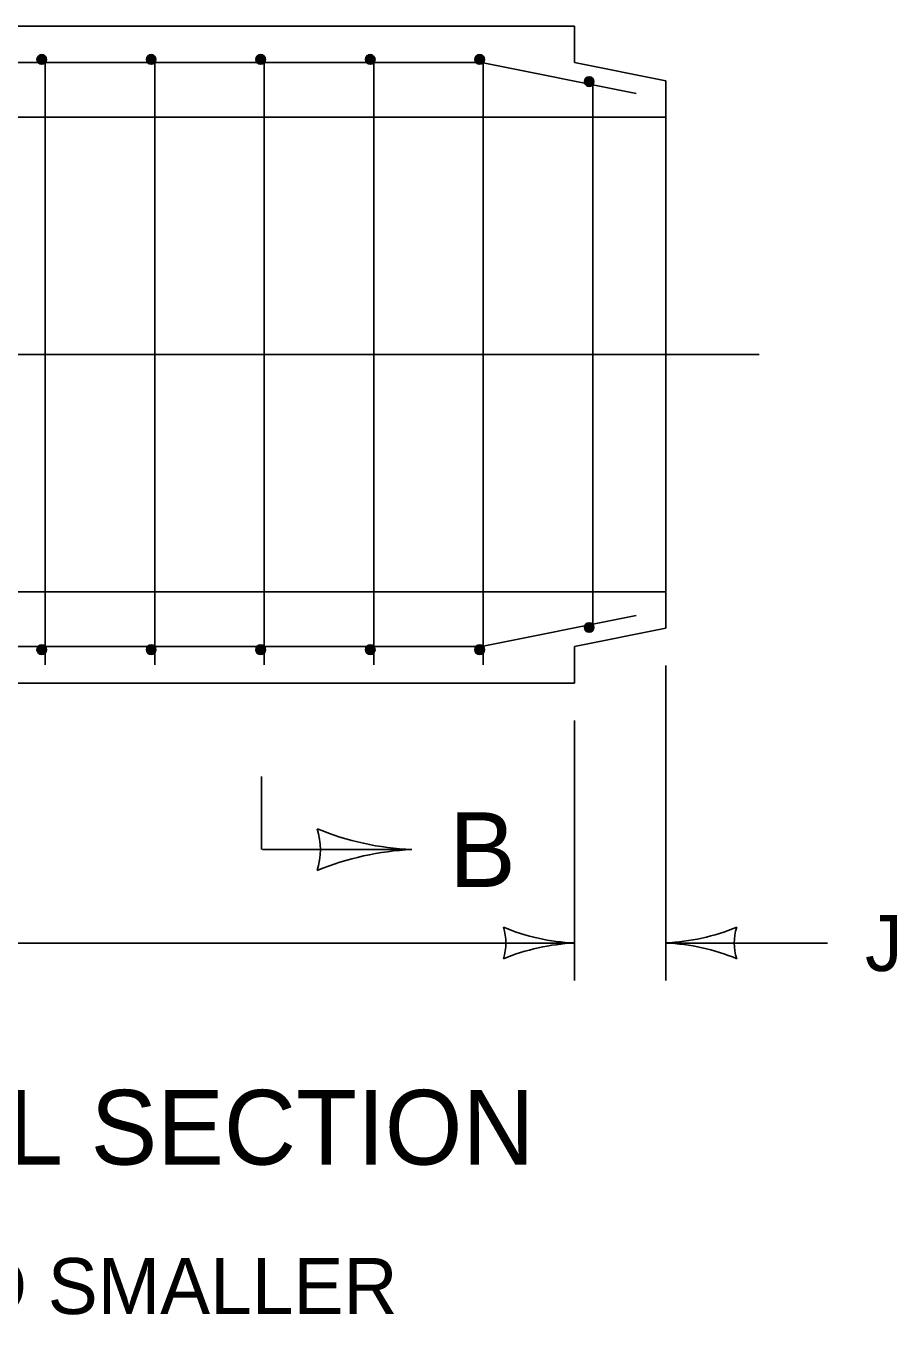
# Model space of a CAD drawing. Extents: x 49991.4 to 50021, y 49987.6 to 50011.4.
# Drawn here: x 50010.952 to 50011.884, y 49993.48 to 49994.877 of the extents above; entities that cross this region are included whole.
import ezdxf

# ---------------------------------------------------------------- set-up
doc = ezdxf.new("R2010")
doc.units = 0
for name, color, linetype in [('Level 1', 7, 'Continuous'), ('Level 2', 7, 'Continuous'), ('Level 3', 7, 'Continuous'), ('Level 5', 7, 'Continuous'), ('Level 6', 7, 'Continuous')]:
    doc.layers.add(name, color=color, linetype=linetype)

msp = doc.modelspace()

# ---------------------------------------------------------------- linework, layer by layer
at = {"layer": 'Level 1'}
for p, q in [((50011.5389, 49994.8774), (50009.7605, 49994.8774)), ((50011.5389, 49994.8384), (50011.5389, 49994.8774)), ((50011.4393, 49994.8384), (50009.9169, 49994.8384)), ((50010.9722, 49994.8384), (50010.9722, 49994.1934)), ((50011.0895, 49994.8384), (50011.0895, 49994.1934)), ((50011.2067, 49994.8384), (50011.2067, 49994.1934)), ((50011.3239, 49994.8384), (50011.3239, 49994.1934)), ((50011.4393, 49994.8384), (50011.6051, 49994.8052)), ((50011.4412, 49994.8384), (50011.4412, 49994.1934)), ((50011.5389, 49994.8384), (50011.6367, 49994.8188)), ((50011.6367, 49994.2326), (50011.6367, 49994.8188)), ((50011.5585, 49994.8145), (50011.5585, 49994.2368)), ((50011.6367, 49994.7798), (50009.8583, 49994.7798)), ((50011.6367, 49994.2716), (50009.8583, 49994.2716)), ((50011.4393, 49994.213), (50011.6051, 49994.2462)), ((50011.6367, 49994.2326), (50011.5389, 49994.213)), ((50011.4393, 49994.213), (50009.9169, 49994.213)), ((50011.5389, 49994.1739), (50011.5389, 49994.213)), ((50011.5389, 49994.1739), (50009.7605, 49994.1739))]:
    msp.add_line(p, q, dxfattribs=at)
for points in [[(50010.9633, 49994.8422), (50010.9679, 49994.8469)], [(50010.9633, 49994.8414), (50010.9688, 49994.8469)], [(50010.9634, 49994.8406), (50010.9695, 49994.8468)], [(50010.9635, 49994.8432), (50010.9669, 49994.8467)], [(50010.9636, 49994.84), (50010.9701, 49994.8466)], [(50010.9639, 49994.8394), (50010.9707, 49994.8464)], [(50010.9641, 49994.8389), (50010.9713, 49994.846)], [(50010.9643, 49994.8449), (50010.9653, 49994.8458), (50010.9653, 49994.8458)], [(50010.9645, 49994.8384), (50010.9645, 49994.8384), (50010.9717, 49994.8457), (50010.9717, 49994.8457)], [(50010.9649, 49994.838), (50010.9649, 49994.838), (50010.9721, 49994.8452), (50010.9721, 49994.8452)], [(50010.9654, 49994.8376), (50010.9725, 49994.8448)], [(50010.9659, 49994.8373), (50010.9729, 49994.8442)], [(50011.0805, 49994.8422), (50011.0852, 49994.8469)], [(50011.0805, 49994.8414), (50011.0861, 49994.8469)], [(50011.0807, 49994.8406), (50011.0868, 49994.8468)], [(50011.0807, 49994.8432), (50011.0842, 49994.8467)], [(50011.0809, 49994.84), (50011.0874, 49994.8466)], [(50011.0811, 49994.8394), (50011.088, 49994.8464)], [(50011.0815, 49994.8389), (50011.0885, 49994.846)], [(50011.0816, 49994.8449), (50011.0825, 49994.8458), (50011.0825, 49994.8458)], [(50011.0817, 49994.8384), (50011.0818, 49994.8384), (50011.0889, 49994.8457), (50011.089, 49994.8457)], [(50011.0821, 49994.838), (50011.0821, 49994.838), (50011.0894, 49994.8452), (50011.0894, 49994.8452)], [(50011.0827, 49994.8376), (50011.0897, 49994.8448)], [(50011.0831, 49994.8373), (50011.0901, 49994.8442)], [(50011.1978, 49994.8422), (50011.2025, 49994.8469)], [(50011.1978, 49994.8414), (50011.2033, 49994.8469)], [(50011.1979, 49994.8406), (50011.2041, 49994.8468)], [(50011.198, 49994.8432), (50011.2015, 49994.8467)], [(50011.1981, 49994.84), (50011.2047, 49994.8466)], [(50011.1983, 49994.8394), (50011.2053, 49994.8464)], [(50011.1987, 49994.8389), (50011.2057, 49994.846)], [(50011.1989, 49994.8449), (50011.1997, 49994.8458), (50011.1998, 49994.8458)], [(50011.199, 49994.8384), (50011.1991, 49994.8384), (50011.2063, 49994.8457), (50011.2063, 49994.8457)], [(50011.1995, 49994.838), (50011.1995, 49994.838), (50011.2067, 49994.8452), (50011.2067, 49994.8452)], [(50011.1999, 49994.8376), (50011.207, 49994.8448)], [(50011.2004, 49994.8373), (50011.2073, 49994.8442)], [(50011.3151, 49994.8422), (50011.3197, 49994.8469)], [(50011.3151, 49994.8414), (50011.3205, 49994.8469)], [(50011.3151, 49994.8406), (50011.3213, 49994.8468)], [(50011.3153, 49994.8432), (50011.3187, 49994.8467)], [(50011.3153, 49994.84), (50011.3219, 49994.8466)], [(50011.3157, 49994.8394), (50011.3225, 49994.8464)], [(50011.3159, 49994.8389), (50011.323, 49994.846)], [(50011.3161, 49994.8449), (50011.317, 49994.8458), (50011.3171, 49994.8458)], [(50011.3163, 49994.8384), (50011.3163, 49994.8384), (50011.3235, 49994.8457), (50011.3235, 49994.8457)], [(50011.3167, 49994.838), (50011.3167, 49994.838), (50011.3239, 49994.8452), (50011.3239, 49994.8452)], [(50011.3171, 49994.8376), (50011.3243, 49994.8448)], [(50011.3177, 49994.8373), (50011.3246, 49994.8442)], [(50011.4323, 49994.8422), (50011.437, 49994.8469)], [(50011.4323, 49994.8414), (50011.4378, 49994.8469)], [(50011.4324, 49994.8406), (50011.4385, 49994.8468)], [(50011.4325, 49994.8432), (50011.4359, 49994.8467)], [(50011.4326, 49994.84), (50011.4391, 49994.8466)], [(50011.4329, 49994.8394), (50011.4397, 49994.8464)], [(50011.4332, 49994.8389), (50011.4403, 49994.846)], [(50011.4333, 49994.8449), (50011.4343, 49994.8458), (50011.4343, 49994.8458)], [(50011.4335, 49994.8384), (50011.4335, 49994.8384), (50011.4407, 49994.8457), (50011.4408, 49994.8457)], [(50011.4339, 49994.838), (50011.4339, 49994.838), (50011.4411, 49994.8452), (50011.4411, 49994.8452)], [(50011.4344, 49994.8376), (50011.4415, 49994.8448)], [(50011.4349, 49994.8373), (50011.4419, 49994.8442)], [(50010.9665, 49994.837), (50010.9731, 49994.8437)], [(50010.9671, 49994.8368), (50010.9733, 49994.8431)], [(50010.9677, 49994.8367), (50010.9735, 49994.8424)], [(50010.9686, 49994.8367), (50010.9735, 49994.8416)], [(50010.9695, 49994.8368), (50010.9733, 49994.8406)], [(50010.9709, 49994.8373), (50010.9729, 49994.8393)], [(50011.0837, 49994.837), (50011.0904, 49994.8437)], [(50011.0843, 49994.8368), (50011.0906, 49994.8431)], [(50011.0851, 49994.8367), (50011.0907, 49994.8424)], [(50011.0859, 49994.8367), (50011.0907, 49994.8416)], [(50011.0868, 49994.8368), (50011.0906, 49994.8406)], [(50011.0881, 49994.8373), (50011.0901, 49994.8393)], [(50011.2009, 49994.837), (50011.2077, 49994.8437)], [(50011.2016, 49994.8368), (50011.2079, 49994.8431)], [(50011.2023, 49994.8367), (50011.2079, 49994.8424)], [(50011.2031, 49994.8367), (50011.208, 49994.8416)], [(50011.2041, 49994.8368), (50011.2079, 49994.8406)], [(50011.2053, 49994.8373), (50011.2073, 49994.8393)], [(50011.3182, 49994.837), (50011.3249, 49994.8437)], [(50011.3189, 49994.8368), (50011.3251, 49994.8431)], [(50011.3195, 49994.8367), (50011.3252, 49994.8424)], [(50011.3203, 49994.8367), (50011.3253, 49994.8416)], [(50011.3213, 49994.8368), (50011.3251, 49994.8406)], [(50011.3226, 49994.8373), (50011.3246, 49994.8393)], [(50011.4355, 49994.837), (50011.4421, 49994.8437)], [(50011.4361, 49994.8368), (50011.4423, 49994.8431)], [(50011.4368, 49994.8367), (50011.4425, 49994.8424)], [(50011.4376, 49994.8367), (50011.4425, 49994.8416)], [(50011.4385, 49994.8368), (50011.4424, 49994.8406)], [(50011.4399, 49994.8373), (50011.4419, 49994.8393)], [(50011.5495, 49994.8176), (50011.5551, 49994.823)], [(50011.5496, 49994.8184), (50011.5543, 49994.823)], [(50011.5497, 49994.8168), (50011.5558, 49994.823)], [(50011.5497, 49994.8194), (50011.5532, 49994.8228)], [(50011.5499, 49994.8162), (50011.5565, 49994.8228)], [(50011.5501, 49994.8156), (50011.557, 49994.8225)], [(50011.5505, 49994.815), (50011.5575, 49994.8222)], [(50011.5506, 49994.821), (50011.5515, 49994.822), (50011.5516, 49994.822)], [(50011.5507, 49994.8146), (50011.5508, 49994.8146), (50011.558, 49994.8218), (50011.5581, 49994.8218)], [(50011.5512, 49994.8142), (50011.5512, 49994.8142), (50011.5584, 49994.8214), (50011.5584, 49994.8214)], [(50011.5517, 49994.8138), (50011.5587, 49994.821)], [(50011.5521, 49994.8134), (50011.5591, 49994.8204)], [(50011.5527, 49994.8132), (50011.5594, 49994.8199)], [(50011.5533, 49994.813), (50011.5596, 49994.8192)], [(50011.5541, 49994.8128), (50011.5597, 49994.8186)], [(50011.5549, 49994.8128), (50011.5597, 49994.8178)], [(50011.5558, 49994.813), (50011.5597, 49994.8168)], [(50011.5571, 49994.8134), (50011.5591, 49994.8154)], [(50011.5495, 49994.2338), (50011.5551, 49994.2284)], [(50011.5496, 49994.233), (50011.5543, 49994.2284)], [(50011.5497, 49994.2346), (50011.5558, 49994.2284)], [(50011.5497, 49994.232), (50011.5532, 49994.2286)], [(50011.5499, 49994.2352), (50011.5565, 49994.2286)], [(50011.5501, 49994.2358), (50011.557, 49994.2289)], [(50011.5505, 49994.2364), (50011.5575, 49994.2292)], [(50011.5506, 49994.2304), (50011.5515, 49994.2294), (50011.5516, 49994.2294)], [(50011.5507, 49994.2368), (50011.5508, 49994.2368), (50011.558, 49994.2296), (50011.5581, 49994.2296)], [(50011.5512, 49994.2372), (50011.5512, 49994.2372), (50011.5584, 49994.23), (50011.5584, 49994.23)], [(50011.5517, 49994.2376), (50011.5587, 49994.2304)], [(50011.5521, 49994.238), (50011.5591, 49994.231)], [(50011.5527, 49994.2382), (50011.5594, 49994.2315)], [(50011.5533, 49994.2384), (50011.5596, 49994.2322)], [(50011.5541, 49994.2386), (50011.5597, 49994.2328)], [(50011.5549, 49994.2386), (50011.5597, 49994.2336)], [(50011.5558, 49994.2384), (50011.5597, 49994.2346)], [(50011.5571, 49994.238), (50011.5591, 49994.236)], [(50010.9633, 49994.21), (50010.9688, 49994.2045)], [(50010.9633, 49994.2092), (50010.9679, 49994.2045)], [(50010.9634, 49994.2108), (50010.9695, 49994.2046)], [(50010.9635, 49994.2082), (50010.9669, 49994.2047)], [(50010.9636, 49994.2114), (50010.9701, 49994.2048)], [(50010.9639, 49994.212), (50010.9707, 49994.205)], [(50010.9641, 49994.2125), (50010.9713, 49994.2054)], [(50010.9643, 49994.2065), (50010.9653, 49994.2056), (50010.9653, 49994.2056)], [(50010.9645, 49994.213), (50010.9645, 49994.213), (50010.9717, 49994.2057), (50010.9717, 49994.2057)], [(50010.9649, 49994.2134), (50010.9649, 49994.2134), (50010.9721, 49994.2062), (50010.9721, 49994.2062)], [(50010.9654, 49994.2138), (50010.9725, 49994.2066)], [(50010.9659, 49994.2141), (50010.9729, 49994.2072)], [(50010.9665, 49994.2144), (50010.9731, 49994.2077)], [(50010.9671, 49994.2146), (50010.9733, 49994.2083)], [(50010.9677, 49994.2147), (50010.9735, 49994.209)], [(50010.9686, 49994.2147), (50010.9735, 49994.2098)], [(50010.9695, 49994.2146), (50010.9733, 49994.2108)], [(50010.9709, 49994.2141), (50010.9729, 49994.2121)], [(50011.0805, 49994.21), (50011.0861, 49994.2045)], [(50011.0805, 49994.2092), (50011.0852, 49994.2045)], [(50011.0807, 49994.2108), (50011.0868, 49994.2046)], [(50011.0807, 49994.2082), (50011.0842, 49994.2047)], [(50011.0809, 49994.2114), (50011.0874, 49994.2048)], [(50011.0811, 49994.212), (50011.088, 49994.205)], [(50011.0815, 49994.2125), (50011.0885, 49994.2054)], [(50011.0816, 49994.2065), (50011.0825, 49994.2056), (50011.0825, 49994.2056)], [(50011.0817, 49994.213), (50011.0818, 49994.213), (50011.0889, 49994.2057), (50011.089, 49994.2057)], [(50011.0821, 49994.2134), (50011.0821, 49994.2134), (50011.0894, 49994.2062), (50011.0894, 49994.2062)], [(50011.0827, 49994.2138), (50011.0897, 49994.2066)], [(50011.0831, 49994.2141), (50011.0901, 49994.2072)], [(50011.0837, 49994.2144), (50011.0904, 49994.2077)], [(50011.0843, 49994.2146), (50011.0906, 49994.2083)], [(50011.0851, 49994.2147), (50011.0907, 49994.209)], [(50011.0859, 49994.2147), (50011.0907, 49994.2098)], [(50011.0868, 49994.2146), (50011.0906, 49994.2108)], [(50011.0881, 49994.2141), (50011.0901, 49994.2121)], [(50011.1978, 49994.21), (50011.2033, 49994.2045)], [(50011.1978, 49994.2092), (50011.2025, 49994.2045)], [(50011.1979, 49994.2108), (50011.2041, 49994.2046)], [(50011.198, 49994.2082), (50011.2015, 49994.2047)], [(50011.1981, 49994.2114), (50011.2047, 49994.2048)], [(50011.1983, 49994.212), (50011.2053, 49994.205)], [(50011.1987, 49994.2125), (50011.2057, 49994.2054)], [(50011.1989, 49994.2065), (50011.1997, 49994.2056), (50011.1998, 49994.2056)], [(50011.199, 49994.213), (50011.1991, 49994.213), (50011.2063, 49994.2057), (50011.2063, 49994.2057)], [(50011.1995, 49994.2134), (50011.1995, 49994.2134), (50011.2067, 49994.2062), (50011.2067, 49994.2062)], [(50011.1999, 49994.2138), (50011.207, 49994.2066)], [(50011.2004, 49994.2141), (50011.2073, 49994.2072)], [(50011.2009, 49994.2144), (50011.2077, 49994.2077)], [(50011.2016, 49994.2146), (50011.2079, 49994.2083)], [(50011.2023, 49994.2147), (50011.2079, 49994.209)], [(50011.2031, 49994.2147), (50011.208, 49994.2098)], [(50011.2041, 49994.2146), (50011.2079, 49994.2108)], [(50011.2053, 49994.2141), (50011.2073, 49994.2121)], [(50011.3151, 49994.2108), (50011.3213, 49994.2046)], [(50011.3151, 49994.21), (50011.3205, 49994.2045)], [(50011.3151, 49994.2092), (50011.3197, 49994.2045)], [(50011.3153, 49994.2114), (50011.3219, 49994.2048)], [(50011.3153, 49994.2082), (50011.3187, 49994.2047)], [(50011.3157, 49994.212), (50011.3225, 49994.205)], [(50011.3159, 49994.2125), (50011.323, 49994.2054)], [(50011.3161, 49994.2065), (50011.317, 49994.2056), (50011.3171, 49994.2056)], [(50011.3163, 49994.213), (50011.3163, 49994.213), (50011.3235, 49994.2057), (50011.3235, 49994.2057)], [(50011.3167, 49994.2134), (50011.3167, 49994.2134), (50011.3239, 49994.2062), (50011.3239, 49994.2062)], [(50011.3171, 49994.2138), (50011.3243, 49994.2066)], [(50011.3177, 49994.2141), (50011.3246, 49994.2072)], [(50011.3182, 49994.2144), (50011.3249, 49994.2077)], [(50011.3189, 49994.2146), (50011.3251, 49994.2083)], [(50011.3195, 49994.2147), (50011.3252, 49994.209)], [(50011.3203, 49994.2147), (50011.3253, 49994.2098)], [(50011.3213, 49994.2146), (50011.3251, 49994.2108)], [(50011.3226, 49994.2141), (50011.3246, 49994.2121)], [(50011.4323, 49994.21), (50011.4378, 49994.2045)], [(50011.4323, 49994.2092), (50011.437, 49994.2045)], [(50011.4324, 49994.2108), (50011.4385, 49994.2046)], [(50011.4325, 49994.2082), (50011.4359, 49994.2047)], [(50011.4326, 49994.2114), (50011.4391, 49994.2048)], [(50011.4329, 49994.212), (50011.4397, 49994.205)], [(50011.4332, 49994.2125), (50011.4403, 49994.2054)], [(50011.4333, 49994.2065), (50011.4343, 49994.2056), (50011.4343, 49994.2056)], [(50011.4335, 49994.213), (50011.4335, 49994.213), (50011.4407, 49994.2057), (50011.4408, 49994.2057)], [(50011.4339, 49994.2134), (50011.4339, 49994.2134), (50011.4411, 49994.2062), (50011.4411, 49994.2062)], [(50011.4344, 49994.2138), (50011.4415, 49994.2066)], [(50011.4349, 49994.2141), (50011.4419, 49994.2072)], [(50011.4355, 49994.2144), (50011.4421, 49994.2077)], [(50011.4361, 49994.2146), (50011.4423, 49994.2083)], [(50011.4368, 49994.2147), (50011.4425, 49994.209)], [(50011.4376, 49994.2147), (50011.4425, 49994.2098)], [(50011.4385, 49994.2146), (50011.4424, 49994.2108)], [(50011.4399, 49994.2141), (50011.4419, 49994.2121)]]:
    msp.add_lwpolyline(points, dxfattribs=at)
for centre in [(50010.9684, 49994.8418), (50011.0856, 49994.8418), (50011.2029, 49994.8418), (50011.3202, 49994.8418), (50011.4374, 49994.8418), (50011.5547, 49994.818), (50011.5547, 49994.2335), (50010.9684, 49994.2097), (50011.0856, 49994.2097), (50011.2029, 49994.2097), (50011.3202, 49994.2097), (50011.4374, 49994.2097)]:
    msp.add_circle(centre, 0.00512, dxfattribs=at)
at = {"layer": 'Level 3'}
for p, q in [((50011.6367, 49994.1926), (50011.6367, 49993.8556)), ((50011.5389, 49994.1339), (50011.5389, 49993.8556)), ((50009.7605, 49993.8956), (50011.5389, 49993.8956)), ((50011.8101, 49993.8956), (50011.6367, 49993.8956))]:
    msp.add_line(p, q, dxfattribs=at)
for centre, radius, start, end in [((50011.3769, 49994.2918), 0.2964, 247.456, 267.6395), ((50011.1938, 49993.9956), 0.073, 342.1388, 17.8612), ((50011.38, 49993.6854), 0.3107, 92.8273, 112.0772), ((50011.5481, 49994.1178), 0.2223, 247.456, 267.6395), ((50011.4107, 49993.8956), 0.0548, 342.1388, 17.8612), ((50011.6252, 49994.1284), 0.233, 272.8273, 292.0772), ((50011.7649, 49993.8956), 0.0548, 162.1388, 197.8612), ((50011.5504, 49993.6629), 0.233, 92.8273, 112.0772), ((50011.6276, 49993.6735), 0.2223, 67.456, 87.6395)]:
    msp.add_arc(centre, radius, start, end, dxfattribs=at)
at = {"layer": 'Level 5'}
msp.add_line((50009.6605, 49994.5257), (50011.7367, 49994.5257), dxfattribs=at)
at = {"layer": 'Level 6'}
for p, q in [((50011.2039, 49993.9956), (50011.2039, 49994.0739)), ((50011.2048, 49993.9956), (50011.3647, 49993.9956))]:
    msp.add_line(p, q, dxfattribs=at)

# ---------------------------------------------------------------- texts
at = {"layer": 'Level 2'}
for s, height, p in [('B', 0.08, (50011.4047, 49993.9556)), ('J', 0.06, (50011.8501, 49993.8656)), ('TYPICAL LONGITUDINAL SECTION', 0.08, (50009.7248, 49993.6583)), ('33" [825] DIAMETER PIPES AND SMALLER', 0.06, (50009.7469, 49993.4983))]:
    msp.add_text(s, height=height, dxfattribs=at).set_placement(p)

doc.saveas('drawing.dxf')
